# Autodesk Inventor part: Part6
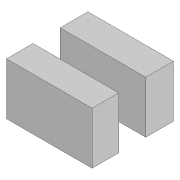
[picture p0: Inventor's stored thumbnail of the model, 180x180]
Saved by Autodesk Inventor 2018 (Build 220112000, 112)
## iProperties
Created: 2015-07
Part Number: Part6
Material: Generic
Document SubType Name: Modeling
Designer: Sandeep
Density: 1 g/cm^3
Appearance: Default
Author: Sandeep
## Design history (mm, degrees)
sketch "Sketch1"
  geometry: L1 (-17.042, 14.133)-(12.609, 14.133); L2 (12.609, 14.133)-(12.609, -14.063); L3 (12.609, -14.063)-(-17.042, -14.063); L4 (-17.042, -14.063)-(-17.042, 14.133); 1 further point
  constraints: 8 end point, 2 parallel, 1 horizontal, 1 perpendicular
extrude "Extrusion1" new body sketch "Sketch1" distance "d0" = 18; taper "d1" = 0 deg
sketch "Sketch2"
  geometry: L1 (-18, 28.196)-(-18, 0) reference; L2 (-18, 9.203)-(0.196, 9.203); L3 (0.196, 9.203)-(0.196, 18.574); L4 (0.196, 18.574)-(-18, 18.574); L5 (-18, 18.574)-(-18, 9.203); 1 further point
  constraints: 8 end point, 2 parallel, 1 horizontal, 1 perpendicular, 1 point on line
extrude "Extrusion2" cut sketch "Sketch2" distance "d2" = 8; taper "d3" = 0 deg
node "Direct Edit1"
body "Solid1"
feature "Delete1"
